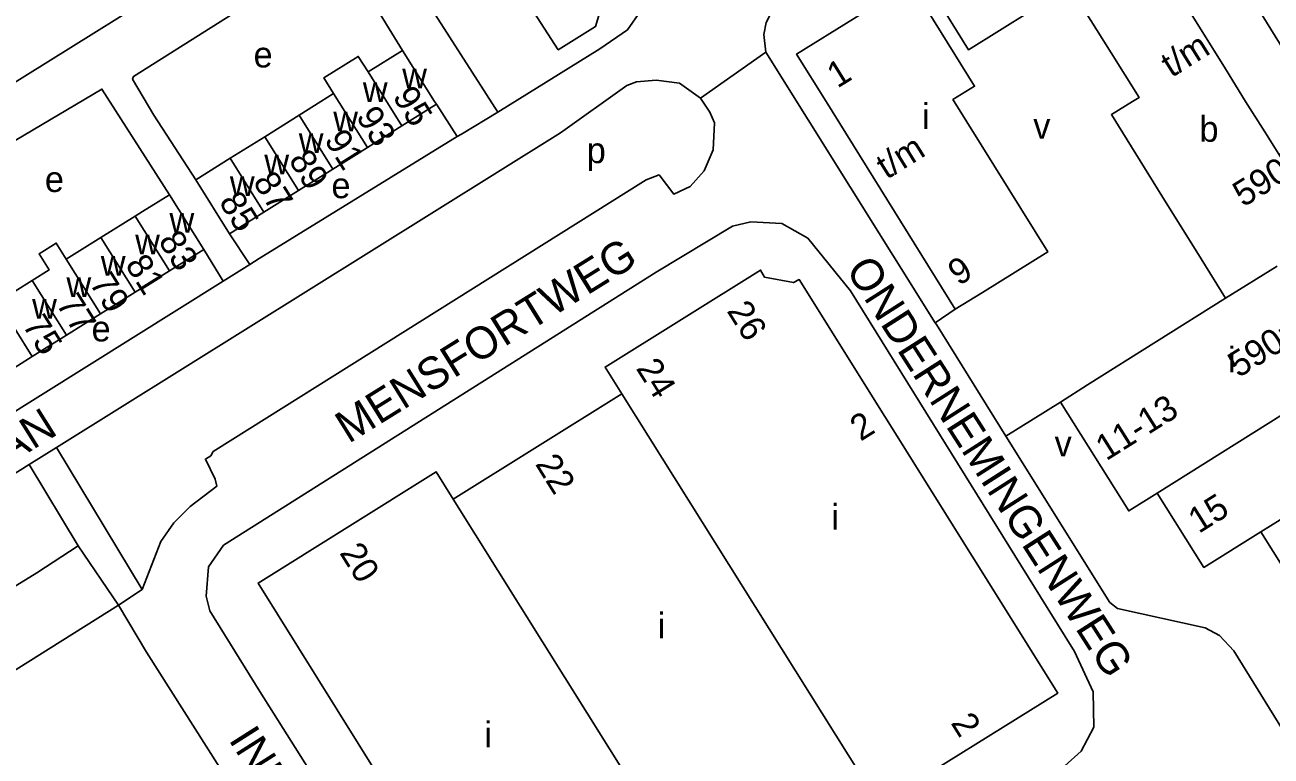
# Model space of a CAD drawing. Extents: x 157768 to 159790, y 387230 to 389604.
# Drawn here: x 158583.5 to 158777.9, y 387897.8 to 388012 of the extents above; entities that cross this region are included whole.
import ezdxf

# ---------------------------------------------------------------- set-up
doc = ezdxf.new("R2010")
doc.units = 0
for name, color, linetype in [('BLT_Basislijn', 7, 'Continuous'), ('BLT_Bebouwing', 7, 'Continuous'), ('BLT_Centroide', 7, 'Continuous'), ('BLT_Huisnummer', 7, 'Continuous'), ('BLT_Huisnummer_ tussenligend', 7, 'Continuous'), ('BLT_Huisnummer_reeks', 7, 'Continuous'), ('BLT_Onderverdeling_panden', 7, 'Continuous'), ('BLT_Straatnaam', 7, 'Continuous'), ('BLT_Vlakafsluiter', 7, 'Continuous')]:
    doc.layers.add(name, color=color, linetype=linetype)

msp = doc.modelspace()

# ---------------------------------------------------------------- linework, layer by layer
at = {"layer": 'BLT_Basislijn'}
for p, q in [((158617.47, 388060.46), (158657.24, 387998.33)), ((158768.38, 388026.72), (158794.66, 387984.08)), ((158642.39, 388007.98), (158632.42, 388024.15)), ((158647.67, 387999.56), (158650.94, 387994.52)), ((158681.97, 387973.33), (158693.86, 387980.56)), ((158693.86, 387980.56), (158696.73, 387981.2)), ((158696.73, 387981.2), (158701.59, 387980.93)), ((158701.59, 387980.93), (158705.65, 387978.65)), ((158615.39, 387979.35), (158618.54, 387974.55)), ((158705.65, 387978.65), (158712.29, 387970.43)), ((158611.38, 387976.91), (158614.42, 387971.95)), ((158618.54, 387974.55), (158614.42, 387971.95)), ((158614.42, 387971.95), (158548.18, 387930.51)), ((158614.47, 387930.75), (158681.97, 387973.33)), ((158712.29, 387970.43), (158741.93, 387922.65)), ((158725.53, 387965.46), (158728.64, 387967.56)), ((158745.05, 387953.08), (158736.54, 387947.74)), ((158588.39, 387945.98), (158584.15, 387943.34)), ((158601.74, 387923.8), (158588.39, 387945.98)), ((158584.15, 387943.34), (158489.29, 387884.1)), ((158591.79, 387930.64), (158584.15, 387943.34)), ((158598.08, 387921.36), (158591.79, 387930.64)), ((158612.14, 387927.32), (158614.47, 387930.75)), ((158611.74, 387922.76), (158612.14, 387927.32)), ((158598.08, 387921.36), (158601.74, 387923.8)), ((158612.34, 387920.46), (158611.74, 387922.76)), ((158741.93, 387922.65), (158747.25, 387914.14)), ((158620.1, 387907.9), (158612.34, 387920.46)), ((158747.25, 387914.14), (158750.19, 387907.82)), ((158652.47, 387856.85), (158620.1, 387907.9)), ((158750.19, 387907.82), (158750.29, 387902.33)), ((158750.29, 387902.33), (158748.27, 387898.56)), ((158748.27, 387898.56), (158745.75, 387896.26))]:
    msp.add_line(p, q, dxfattribs=at)
for points in [[(158617.47, 388060.46), (158640.43, 388075.18), (158642.63, 388075.35), (158643.63, 388075.09), (158647.96, 388068.92), (158679.39, 388020.48), (158679.87, 388019.2), (158679.55, 388014.1), (158677.48, 388011.18), (158673.17, 388008.21), (158657.24, 387998.33)], [(158555.74, 388003.46), (158564.09, 387991.42), (158564.65, 387992.22), (158627.78, 388031.66)], [(158699.08, 388007.71), (158698.76, 388010.45), (158699.12, 388012.33), (158700.31, 388014.67), (158701.68, 388016.01), (158717.26, 388025.27)], [(158632.42, 388024.15), (158600.43, 388003.92), (158600.27, 388003.49), (158603.56, 387997.89), (158610.12, 387987.76)], [(158725.53, 387965.46), (158699.08, 388007.71)], [(158688.91, 388000.54), (158685.62, 388002.85), (158681.95, 388003.32), (158678.91, 388003.05), (158677.4, 388002.5), (158667.03, 387995.09), (158588.39, 387945.98)], [(158606.04, 387985.45), (158595.47, 388001.94), (158581.96, 387993.9), (158529.77, 387960.39)], [(158601.74, 387923.8), (158604.67, 387931.32), (158606.7, 387934.22), (158609.23, 387936.78), (158613.4, 387939.93), (158613.15, 387941.01), (158611.63, 387944.16), (158612.47, 387944.7), (158612.85, 387945.33), (158680.41, 387987.75), (158682.43, 387988.55), (158684.74, 387985.51), (158687.29, 387986.75), (158689.45, 387989.19), (158690.87, 387992.44), (158691.05, 387996.69), (158690.35, 387998.31), (158688.91, 388000.54)], [(158657.24, 387998.33), (158651.57, 387994.91), (158650.94, 387994.52)], [(158650.94, 387994.52), (158620.01, 387975.48), (158618.54, 387974.55)], [(158736.54, 387947.74), (158725.7, 387965.18), (158725.53, 387965.46)], [(158783.83, 387895.33), (158783.26, 387896.24), (158772.1, 387914.24), (158769.86, 387916.63), (158767.63, 387917.81), (158753.96, 387920.85), (158752.75, 387921.79), (158736.54, 387947.74)], [(158591.79, 387930.64), (158585.33, 387926.39), (158512.6, 387881.66), (158512.7, 387881.03), (158515.79, 387876.07)]]:
    msp.add_lwpolyline(points, dxfattribs=at)
at = {"layer": 'BLT_Bebouwing'}
for p, q in [((158746.56, 388017.93), (158752.97, 388007.62)), ((158770.8, 388005.08), (158764.69, 388014.92)), ((158642.39, 388007.98), (158637.02, 388004.61)), ((158647.67, 387999.56), (158642.29, 387996.19)), ((158620.88, 387994.5), (158626.26, 387997.87)), ((158642.29, 387996.19), (158636.91, 387992.82)), ((158776.93, 387995.26), (158783.08, 387985.46)), ((158615.5, 387991.13), (158620.88, 387994.5)), ((158754.79, 387995.11), (158760.9, 387985.28)), ((158636.91, 387992.82), (158631.53, 387989.45)), ((158610.12, 387987.76), (158615.5, 387991.13)), ((158631.53, 387989.45), (158626.15, 387986.08)), ((158615.39, 387979.35), (158610.12, 387987.76)), ((158626.15, 387986.08), (158620.77, 387982.72)), ((158611.38, 387976.91), (158606.04, 387985.45)), ((158760.9, 387985.28), (158767, 387975.46)), ((158600.69, 387982.11), (158595.33, 387978.76)), ((158620.77, 387982.72), (158615.39, 387979.35)), ((158595.33, 387978.76), (158589.92, 387975.38)), ((158606.03, 387973.57), (158611.38, 387976.91)), ((158767, 387975.46), (158770.84, 387969.28)), ((158584.61, 387972.06), (158579.25, 387968.71)), ((158600.67, 387970.21), (158606.03, 387973.57)), ((158595.25, 387966.83), (158600.67, 387970.21)), ((158589.95, 387963.51), (158595.25, 387966.83)), ((158584.59, 387960.16), (158589.95, 387963.51)), ((158579.23, 387956.81), (158584.59, 387960.16)), ((158650.31, 387937.93), (158676.61, 387954.35)), ((158783.11, 387921.97), (158776.31, 387932.81)), ((158602.44, 387914.04), (158598.08, 387921.36)), ((158616.01, 387892.68), (158602.44, 387914.04))]:
    msp.add_line(p, q, dxfattribs=at)
for points in [[(158661.26, 388016.51), (158666.69, 388008.09), (158672.49, 388011.71), (158673.36, 388014.45), (158672.44, 388015.93), (158673.05, 388016.31), (158669.67, 388021.75)], [(158723.54, 388019.6), (158726.03, 388015.59), (158730.7, 388008.07), (158740.36, 388014.08)], [(158721.67, 388018.46), (158703.88, 388007.4), (158708.48, 388000), (158728.64, 387967.56)], [(158728.64, 387967.56), (158732.89, 387970.2), (158743.07, 387976.52), (158728.47, 388000), (158728.29, 388000.3), (158731.65, 388002.39), (158724.31, 388014.21), (158721.67, 388018.46)], [(158637.02, 388004.61), (158635.47, 388007.05), (158630.12, 388003.7), (158631.64, 388001.24)], [(158647.67, 387999.56), (158647.39, 388000), (158642.39, 388007.98)], [(158752.97, 388007.62), (158757.32, 388000.62), (158756.32, 388000), (158753.02, 387997.95), (158754.79, 387995.11)], [(158776.93, 387995.26), (158773.95, 388000), (158770.8, 388005.08)], [(158626.26, 387997.87), (158629.66, 388000), (158631.64, 388001.24)], [(158606.04, 387985.45), (158601.8, 387982.8), (158600.69, 387982.11)], [(158589.92, 387975.38), (158588.35, 387977.89), (158585.68, 387976.22), (158587.25, 387973.71), (158584.61, 387972.06)], [(158676.61, 387954.35), (158673.99, 387958.54), (158698.27, 387973.69), (158698.86, 387972.58), (158703.38, 387971.73), (158704.3, 387972.2), (158744.63, 387907.64), (158716.74, 387890.25), (158714.1, 387894.49)], [(158745.05, 387953.08), (158749.28, 387955.74), (158770.84, 387969.28)], [(158760.15, 387938.87), (158755.72, 387936.08), (158745.05, 387953.08)], [(158687.77, 387878.04), (158690.43, 387873.79), (158662.45, 387856.35), (158643.85, 387886.18), (158641.54, 387884.73), (158636.1, 387893.45), (158638.48, 387894.94), (158619.84, 387924.8), (158647.66, 387942.17), (158650.31, 387937.93)], [(158776.31, 387932.81), (158767.45, 387927.25), (158760.15, 387938.87)], [(158598.08, 387921.36), (158573.38, 387905.85), (158591.71, 387876.58), (158584.31, 387871.94), (158594.08, 387856.34)]]:
    msp.add_lwpolyline(points, dxfattribs=at)
at = {"layer": 'BLT_Onderverdeling_panden'}
for p, q in [((158642.29, 387996.19), (158637.02, 388004.61)), ((158636.91, 387992.82), (158631.64, 388001.24)), ((158631.53, 387989.45), (158626.26, 387997.87)), ((158626.15, 387986.08), (158620.88, 387994.5)), ((158620.77, 387982.72), (158615.5, 387991.13)), ((158606.03, 387973.57), (158600.69, 387982.11)), ((158600.67, 387970.21), (158595.33, 387978.76)), ((158595.25, 387966.83), (158589.92, 387975.38)), ((158770.84, 387969.28), (158778.9, 387974.28)), ((158589.95, 387963.51), (158584.61, 387972.06)), ((158584.59, 387960.16), (158579.25, 387968.71)), ((158797.52, 387962.36), (158760.15, 387938.87)), ((158676.61, 387954.35), (158714.1, 387894.49)), ((158799.86, 387947.47), (158776.31, 387932.81)), ((158650.31, 387937.93), (158687.77, 387878.04))]:
    msp.add_line(p, q, dxfattribs=at)
at = {"layer": 'BLT_Vlakafsluiter'}
msp.add_line((158699.08, 388007.71), (158688.91, 388000.54), dxfattribs=at)

# ---------------------------------------------------------------- texts
at = {"layer": 'BLT_Centroide'}
for s, p in [('e', (158619.15, 388005.32)), ('w', (158642.34, 388002.08)), ('w', (158636.2, 387999.92)), ('i', (158723.47, 387995.72)), ('w', (158631.58, 387995.36)), ('v', (158740.82, 387994.18)), ('b', (158766.75, 387993.72)), ('w', (158626.2, 387991.98)), ('p', (158671.13, 387990.38)), ('w', (158620.83, 387988.61)), ('e', (158586.58, 387985.87)), ('w', (158615.45, 387985.23)), ('e', (158631.3, 387984.9)), ('w', (158606.03, 387979.5)), ('w', (158600.67, 387976.16)), ('w', (158595.31, 387972.81)), ('w', (158589.95, 387969.47)), ('w', (158584.59, 387966.11)), ('e', (158593.87, 387962.54)), ('i', (158771.23, 387957.69)), ('v', (158744.15, 387944.59)), ('i', (158709.31, 387933.14)), ('i', (158682.2, 387916.17)), ('i', (158655.14, 387899.16))]:
    msp.add_text(s, height=4, dxfattribs=at).set_placement(p)
at = {"layer": 'BLT_Huisnummer'}
for s, rotation, p in [('95', 302.058, (158640.75, 388000.77)), ('89', 302.058, (158624.52, 387990.86)), ('85', 302.058, (158613.64, 387984.34)), ('83', 302.0114, (158604.19, 387978.24)), ('77', 302.0114, (158588.25, 387968.41)), ('15', 32.1174, (158766.64, 387932.46))]:
    msp.add_text(s, height=4, rotation=rotation, dxfattribs=at).set_placement(p)
at = {"layer": 'BLT_Huisnummer_ tussenligend'}
for s, rotation, p in [('93', 302.058, (158635.04, 387997.66)), ('91', 302.058, (158630.09, 387994.02)), ('87', 302.058, (158618.96, 387987.46)), ('81', 302.0114, (158599.01, 387974.53)), ('79', 302.0114, (158593.44, 387971.66)), ('75', 302.0114, (158582.98, 387965.1))]:
    msp.add_text(s, height=4, rotation=rotation, dxfattribs=at).set_placement(p)
at = {"layer": 'BLT_Huisnummer_reeks'}
for s, rotation, p in [('t/m', 31.9343, (158762.38, 388003.65)), ('1', 31.865, (158710.25, 388001.99)), ('t/m', 31.865, (158717.94, 387987.75)), ('590l', 31.9343, (158773.58, 387983.42)), ('9', 32.6923, (158729.19, 387971.13)), ('590m-n-592', 32.1609, (158772.84, 387956.77)), ('26', 302.0603, (158692.91, 387967.31)), ('24', 302.0603, (158678.74, 387958.34)), ('11-13', 32.1272, (158752.2, 387943.81)), ('2', 31.9477, (158713.87, 387946.87)), ('22', 301.9738, (158663.01, 387943.4)), ('20', 302.0317, (158632.47, 387929.53)), ('2', 301.9544, (158727.86, 387902.98))]:
    msp.add_text(s, height=4, rotation=rotation, dxfattribs=at).set_placement(p)
at = {"layer": 'BLT_Straatnaam'}
for s, height, rotation, p in [('MENSFORTWEG', 4.9999, 31.8955, (158633.98, 387946.52)), ('ONDERNEMINGENWEG', 5, 302.6093, (158711.45, 387973.77)), ('CAHORSLAAN', 5, 32.0348, (158549.76, 387923.71)), ('INDUSTRIEWEG', 5, 302.3854, (158615.16, 387900.38))]:
    msp.add_text(s, height=height, rotation=rotation, dxfattribs=at).set_placement(p)

doc.saveas('drawing.dxf')
